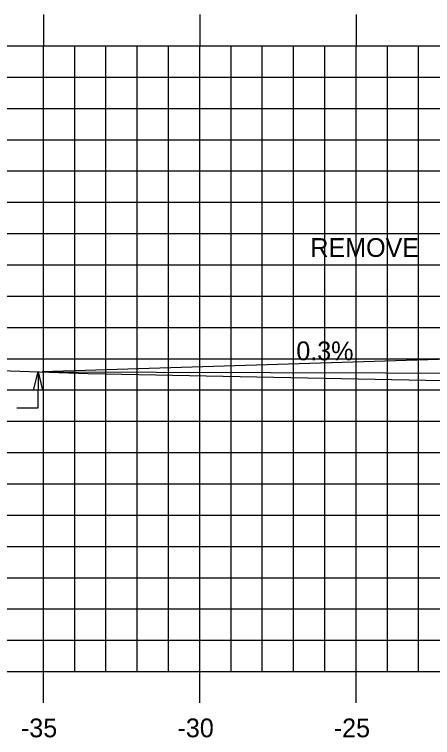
# Model space of a CAD drawing. Extents: x 1138985 to 1139155, y 608981 to 609091.
# Drawn here: x 1139032.02 to 1139045.39, y 609048.23 to 609071.34 of the extents above; entities that cross this region are included whole.
import ezdxf

# ---------------------------------------------------------------- set-up
doc = ezdxf.new("R2010")
doc.units = 0
for name, color, linetype in [('ANNOTATION', 7, 'Continuous'), ('D_Roadway_SlopeLines', 7, 'Continuous'), ('D_Text_Standard', 7, 'Continuous'), ('H_V ANNOTATION', 7, 'Continuous'), ('MAJOR', 7, 'Continuous'), ('MINOR', 7, 'Continuous'), ('S_Roadway_Centerline', 7, 'Continuous')]:
    doc.layers.add(name, color=color, linetype=linetype)

msp = doc.modelspace()

# ---------------------------------------------------------------- linework, layer by layer
msp.add_lwpolyline([(1139032.911, 609059.91), (1139051.198, 609059.859), (1139051.199, 609059.859), (1139051.403, 609060.487), (1139051.699, 609060.499), (1139051.949, 609059.889), (1139056.949, 609060.089), (1139067.949, 609060.309), (1139078.949, 609060.089), (1139082.949, 609059.929), (1139090.672, 609057.354), (1139093.672, 609056.354), (1139094.967, 609057.001), (1139096.217, 609057.56), (1139097.467, 609057.986), (1139098.717, 609058.28), (1139099.967, 609058.441)])
at = {"layer": 'D_Roadway_SlopeLines'}
msp.add_lwpolyline([(1139051.403, 609060.487), (1139032.911, 609059.91)], dxfattribs=at)
at = {"layer": 'D_Text_Standard'}
msp.add_lwpolyline([(1139032.777, 609059.915), (1139032.774, 609058.751), (1139032.094, 609058.751)], dxfattribs=at)
msp.add_lwpolyline([(1139032.777, 609059.915), (1139032.921, 609059.332), (1139032.63, 609059.333)], close=True, dxfattribs=at)
at = {"layer": 'MAJOR'}
for p, q in [((1139032.949, 609071.337), (1139032.949, 609070.335)), ((1139037.949, 609071.337), (1139037.949, 609070.335)), ((1139042.949, 609071.337), (1139042.949, 609070.335)), ((1138997.949, 609070.335), (1139137.949, 609070.335)), ((1138997.949, 609070.335), (1139137.949, 609070.335)), ((1139032.949, 609050.335), (1139032.949, 609070.335)), ((1139037.949, 609050.335), (1139037.949, 609070.335)), ((1139042.949, 609050.335), (1139042.949, 609070.335)), ((1138997.949, 609065.335), (1139137.949, 609065.335)), ((1138997.949, 609060.335), (1139137.949, 609060.335)), ((1138997.949, 609055.335), (1139137.949, 609055.335)), ((1138997.949, 609050.335), (1139137.949, 609050.335)), ((1138997.949, 609050.335), (1139137.949, 609050.335)), ((1139032.949, 609049.333), (1139032.949, 609050.335)), ((1139037.949, 609049.333), (1139037.949, 609050.335)), ((1139042.949, 609049.333), (1139042.949, 609050.335))]:
    msp.add_line(p, q, dxfattribs=at)
at = {"layer": 'MINOR'}
for p, q in [((1139033.949, 609050.335), (1139033.949, 609070.335)), ((1139034.949, 609050.335), (1139034.949, 609070.335)), ((1139035.949, 609050.335), (1139035.949, 609070.335)), ((1139036.949, 609050.335), (1139036.949, 609070.335)), ((1139038.949, 609050.335), (1139038.949, 609070.335)), ((1139039.949, 609050.335), (1139039.949, 609070.335)), ((1139040.949, 609050.335), (1139040.949, 609070.335)), ((1139041.949, 609050.335), (1139041.949, 609070.335)), ((1139043.949, 609050.335), (1139043.949, 609070.335)), ((1139044.949, 609050.335), (1139044.949, 609070.335)), ((1138997.949, 609069.335), (1139137.949, 609069.335)), ((1138997.949, 609068.335), (1139137.949, 609068.335)), ((1138997.949, 609067.335), (1139137.949, 609067.335)), ((1138997.949, 609066.335), (1139137.949, 609066.335)), ((1138997.949, 609064.335), (1139137.949, 609064.335)), ((1138997.949, 609063.335), (1139137.949, 609063.335)), ((1138997.949, 609062.335), (1139137.949, 609062.335)), ((1138997.949, 609061.335), (1139137.949, 609061.335)), ((1138997.949, 609059.335), (1139137.949, 609059.335)), ((1138997.949, 609058.335), (1139137.949, 609058.335)), ((1138997.949, 609057.335), (1139137.949, 609057.335)), ((1138997.949, 609056.335), (1139137.949, 609056.335)), ((1138997.949, 609054.335), (1139137.949, 609054.335)), ((1138997.949, 609053.335), (1139137.949, 609053.335)), ((1138997.949, 609052.335), (1139137.949, 609052.335)), ((1138997.949, 609051.335), (1139137.949, 609051.335))]:
    msp.add_line(p, q, dxfattribs=at)
at = {"layer": 'S_Roadway_Centerline'}
msp.add_lwpolyline([(1139016.434, 609060.334), (1139031.885, 609059.945), (1139034.377, 609059.859), (1139052.189, 609059.505), (1139054.799, 609059.411), (1139055.727, 609059.439), (1139059.616, 609059.763), (1139066.017, 609059.781), (1139070.197, 609059.83), (1139070.369, 609060.059), (1139076.793, 609059.71), (1139080.407, 609059.613), (1139083.326, 609059.173), (1139084.343, 609059.069), (1139087.733, 609057.962), (1139089.051, 609057.481), (1139090.872, 609057.361), (1139093.183, 609057.505), (1139095.448, 609057.872), (1139096.555, 609058.182), (1139104.125, 609058.757), (1139115.082, 609058.5), (1139137.949, 609058.777)], dxfattribs=at)

# ---------------------------------------------------------------- texts
at = {"layer": 'ANNOTATION'}
msp.add_text('0.3%', height=0.6, rotation=359.8394, dxfattribs=at).set_placement((1139041.035, 609060.287))
at = {"layer": 'D_Text_Standard'}
msp.add_text('REMOVE', height=0.6, dxfattribs=at).set_placement((1139041.485, 609063.588))
at = {"layer": 'H_V ANNOTATION'}
for s, p in [('-35', (1139032.229, 609048.235)), ('-30', (1139037.237, 609048.235)), ('-25', (1139042.234, 609048.235))]:
    msp.add_text(s, height=0.6, dxfattribs=at).set_placement(p)

doc.saveas('drawing.dxf')
